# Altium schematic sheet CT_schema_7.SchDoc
size 387 x 301 mm
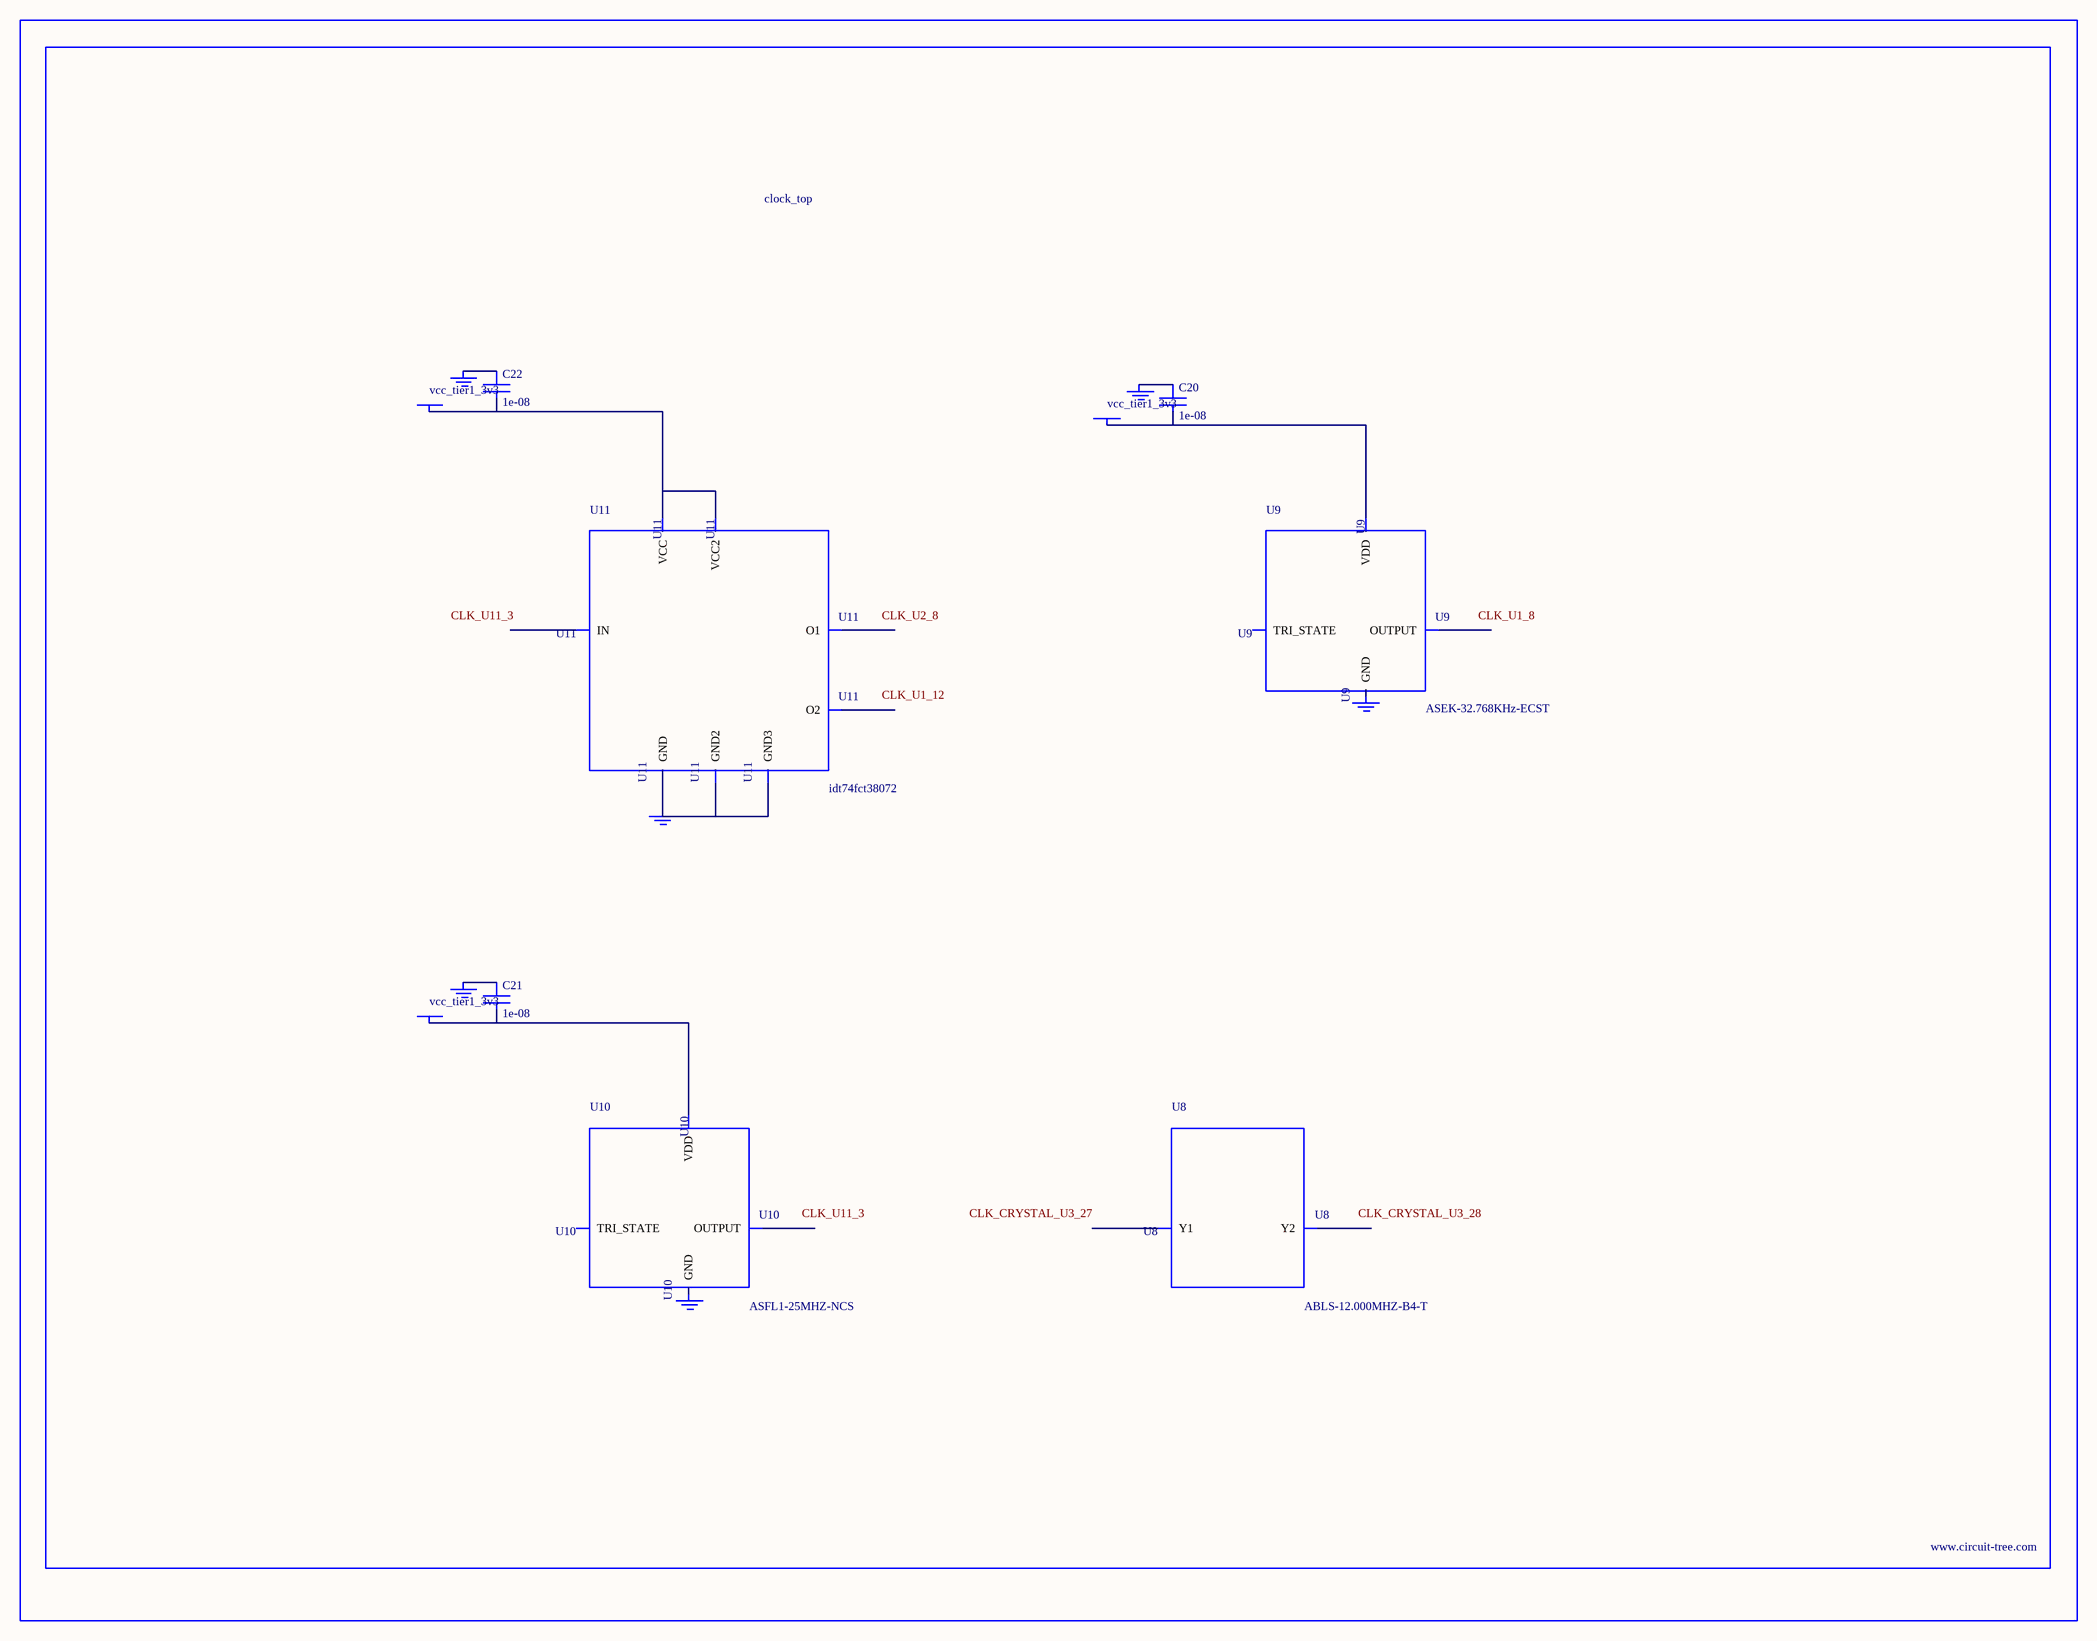
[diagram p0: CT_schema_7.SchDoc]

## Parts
BORDER6  (no value)
C20  1e-08  [C0402]
C21  1e-08  [C0402]
C22  1e-08  [C0402]
GND_INSTANCE_6_0  (no value)
GND_INSTANCE_6_1  (no value)
GND_INSTANCE_6_2  (no value)
GND_INSTANCE_6_3  (no value)
GND_INSTANCE_6_4  (no value)
GND_INSTANCE_6_5  (no value)
POWER_INSTANCE_6_0  vcc_tier1_3v3
POWER_INSTANCE_6_1  vcc_tier1_3v3
POWER_INSTANCE_6_2  vcc_tier1_3v3
U8  ABLS-12.000MHZ-B4-T  [ABLS-12.000MHZ-B4-T]
U9  ASEK-32.768KHz-ECST  [ASEK]
U10  ASFL1-25MHZ-NCS  [ASFL1]
U11  idt74fct38072  [IDT74FCT38072]

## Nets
NetC20_1: C20.1 GND_INSTANCE_6_0.0(GND)
NetC20_2: C20.2 POWER_INSTANCE_6_0.0(PWR) U9.4(VDD)
NetC21_1: C21.1 GND_INSTANCE_6_2.0(GND)
NetC21_2: C21.2 POWER_INSTANCE_6_1.0(PWR) U10.4(VDD)
NetC22_1: C22.1 GND_INSTANCE_6_4.0(GND)
NetC22_2: C22.2 POWER_INSTANCE_6_2.0(PWR) U11.1(VCC) U11.2(VCC2)
NetGND_INSTANCE_6_5_0: GND_INSTANCE_6_5.0(GND) U11.4(GND) U11.5(GND2) U11.8(GND3)

Not connected (* = marked no-connect by the designer): GND_INSTANCE_6_1 0(GND); GND_INSTANCE_6_3 0(GND); U8 1(Y1) 2(Y2); U9 1(TRI_STATE) 2(GND) 3(OUTPUT); U10 1(TRI_STATE) 2(GND) 3(OUTPUT); U11 3(IN) 6(O2) 7(O1)

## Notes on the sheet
- Labels drawn without touching a wire or pin: CLK_CRYSTAL_U3_27, CLK_CRYSTAL_U3_28, CLK_U1_8, CLK_U1_12, CLK_U2_8, CLK_U11_3

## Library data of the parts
BORDER6 = BORDER_PAGE6
C20-C22 = C0402C103K3RAC
GND_INSTANCE_6_0-GND_INSTANCE_6_5 = GND
POWER_INSTANCE_6_0-POWER_INSTANCE_6_2 = PWR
